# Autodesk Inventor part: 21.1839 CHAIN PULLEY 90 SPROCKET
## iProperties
Created: 2007-05
Part Number: 21.1839 CHAIN PULLEY 90 SPROCKET
Document SubType Name: Modeling
Designer: Andy Moles
Material: Steel
Density: 7.85 g/cm^3
Mass: 182.761 g
Surface Area: 100.461 cm^2
Volume: 23.2816 cm^3
Author: Andy Moles
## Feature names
1. Extrusion1
2. Extrusion2
3. Circular Pattern1
4. Extrusion3
5. Extrusion4
6. Mirror1
